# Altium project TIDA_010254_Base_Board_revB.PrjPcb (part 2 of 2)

## Sheet TIDA_010254_Base_Board_Sensors.SchDoc: Sensors
size 431 x 279 mm; Date: Not shown in title block; ApprovedBy: Not shown in title block; CheckedBy: Not shown in title block; Author: Not shown in title block; CompanyName: Not shown in title block; DrawnBy: Justin Yin; Engineer: Not shown in title block; Organization: Not shown in title block; Address1: Not shown in title block; Address2: Not shown in title block; Address3: Not shown in title block; Address4: Not shown in title block; DocumentNumber: 7; Revision: Use project parameter SCH_Rev; SheetNumber: 7; SheetTotal: 8; PageSetup: Record=PageOptions¦CenterHorizontal=True¦CenterVertical=True¦PrintScale=1.00¦XCorrection=1.00¦YCorrection=1.00¦PrintKind=0¦BorderSize=5000000¦LeftOffset=0¦BottomOffset=0¦Orientation=2¦PaperLength=1000¦PaperWidth=1000¦Scale=100¦PaperSource=15¦PrintQuality=600¦MediaType=1¦DitherType=10¦PaperKind=Letter¦PrintScaleMode=1
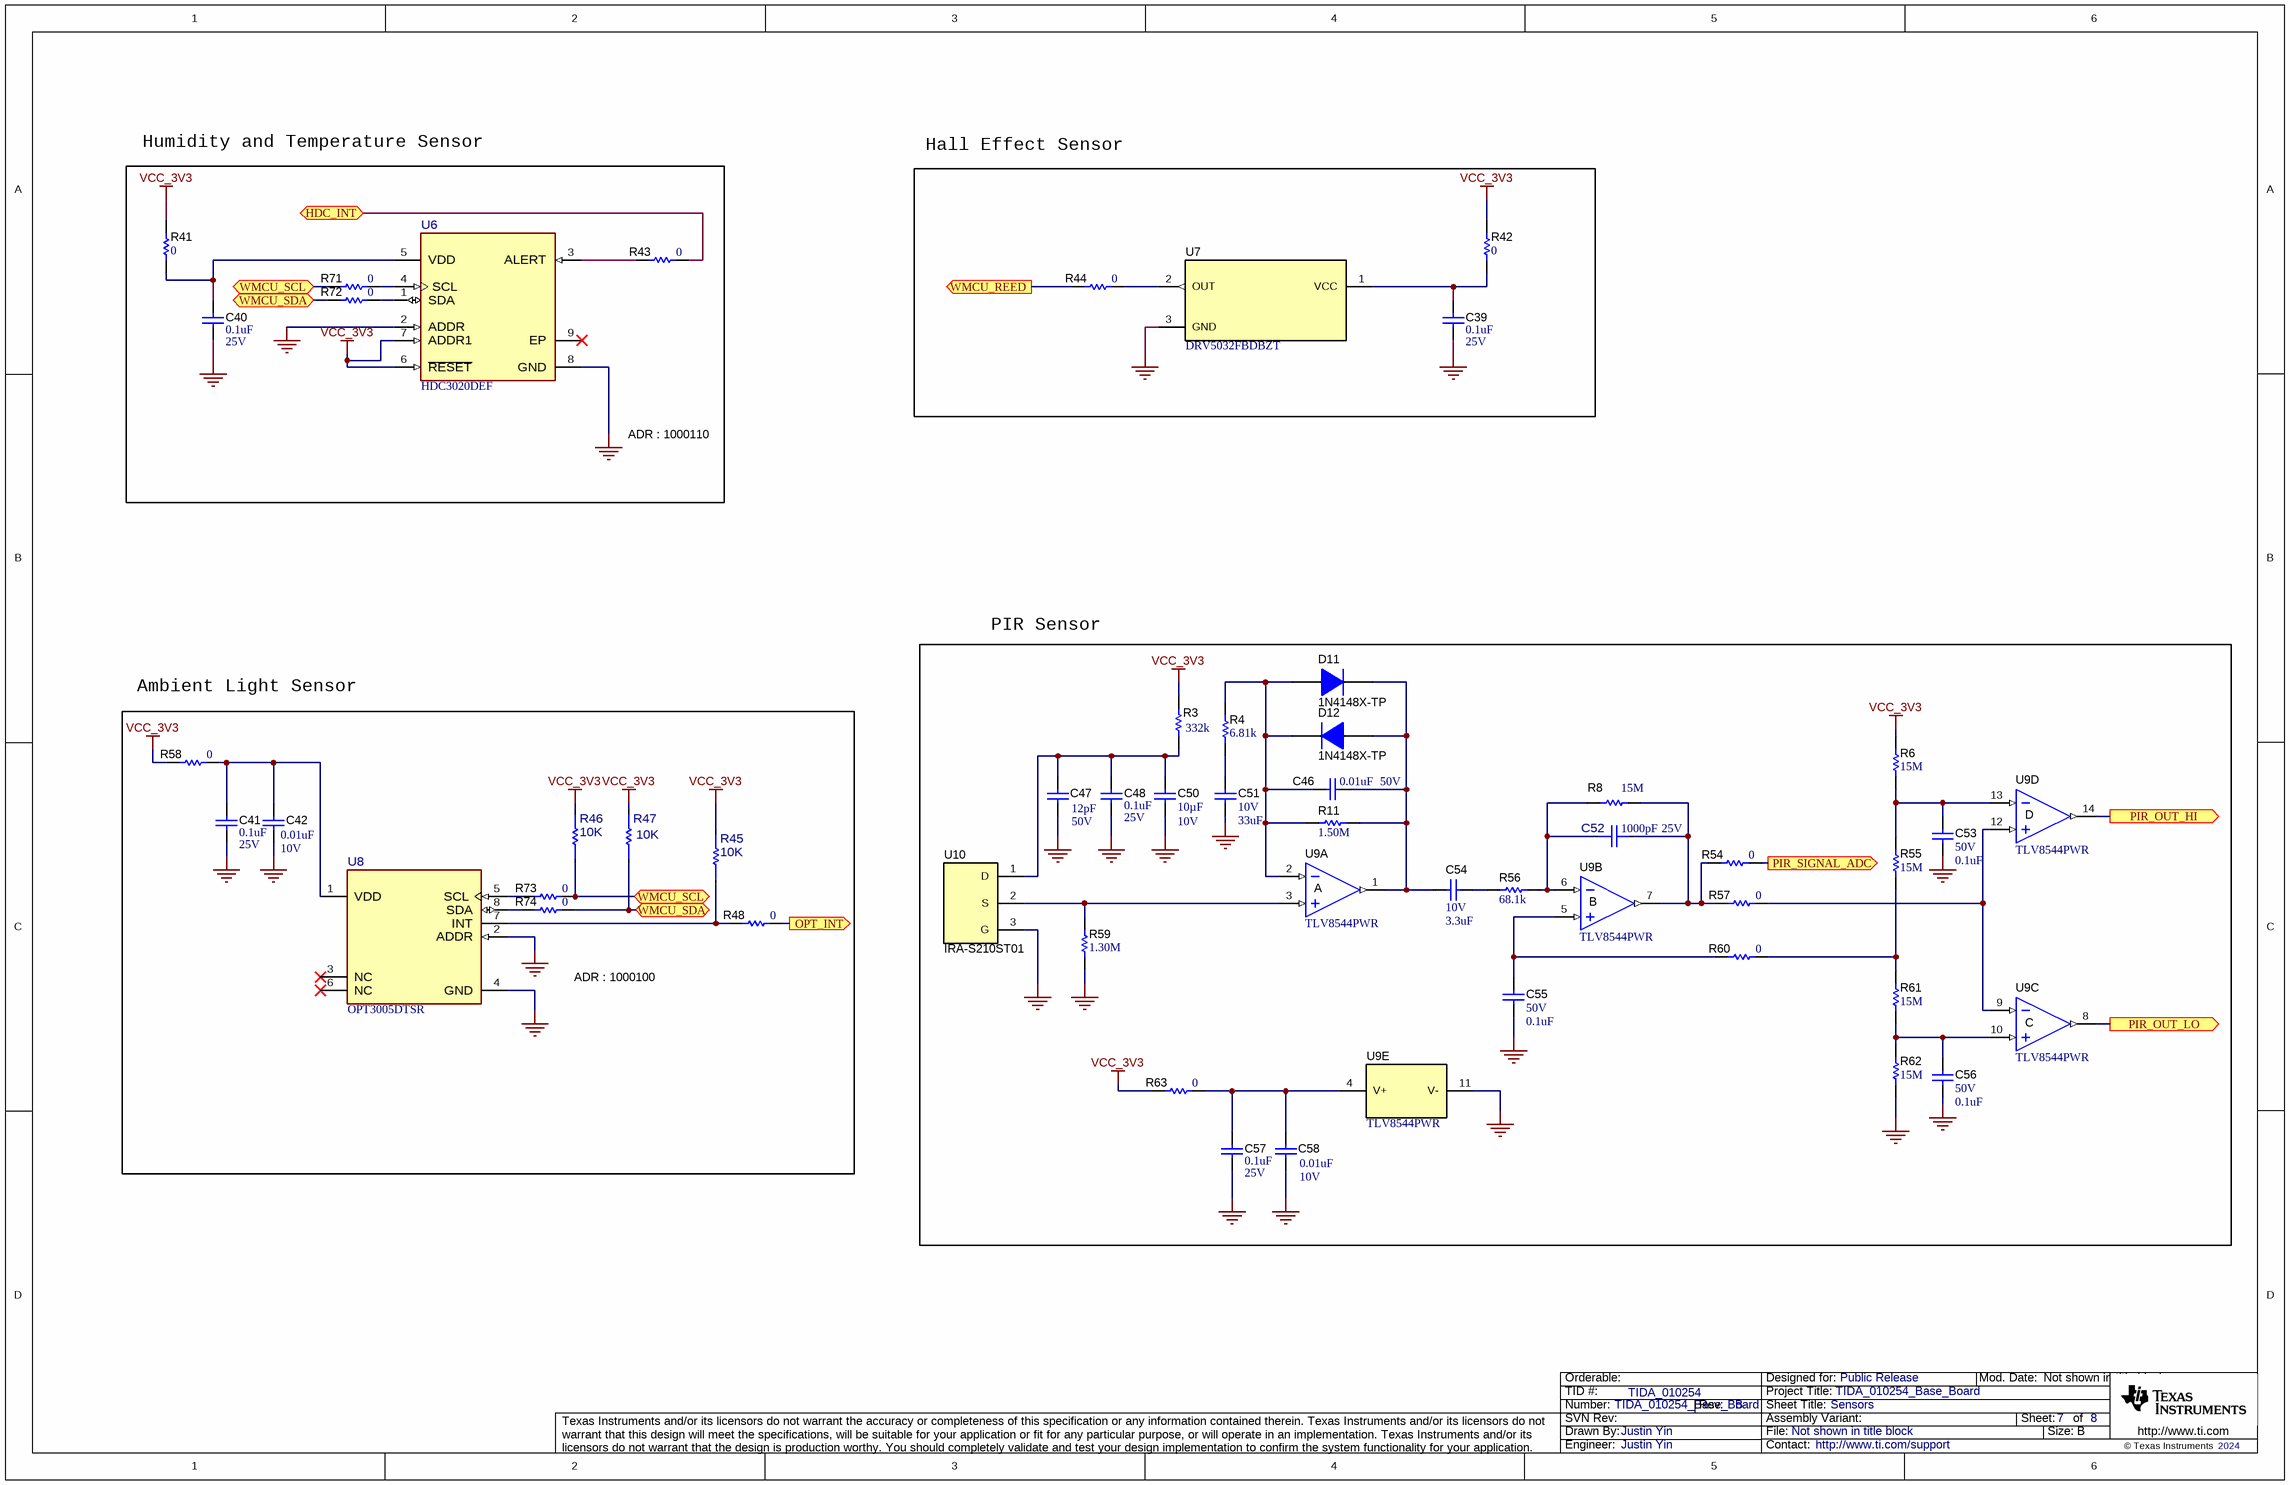
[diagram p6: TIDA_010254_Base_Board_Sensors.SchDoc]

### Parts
C39  VDC_V: 25V  ValueDisplayed: 0.1uF  [0402]  (hidden comment: GRM155R71E104KE14D)
C40  VDC_V: 25V  ValueDisplayed: 0.1uF  [0402]  (hidden comment: GRM155R71E104KE14D)
C41  VDC_V: 25V  ValueDisplayed: 0.1uF  [0402]  (hidden comment: GRM155R71E104KE14D)
C42  VDC_V: 10V  ValueDisplayed: 0.01uF  [0201]  (hidden comment: GRM033R61A103KA01D)
C46  VDC_V: 50V  ValueDisplayed: 0.01uF  [0402]  (hidden comment: GRM155R71H103KA88D)
C47  VDC_V: 50V  ValueDisplayed: 12pF  [0402]  (hidden comment: GRM1555C1H120JA01D)
C48  VDC_V: 25V  ValueDisplayed: 0.1uF  [0402]  (hidden comment: GRM155R71E104KE14D)
C50  Cap_F: 10µF  VDC_V: 10V  [0805_HV]  (hidden comment: GRM21BR71A106KA73L)
C51  VDC_V: 10V  ValueDisplayed: 33uF  [0805_HV]  (hidden comment: C2012X5R1A336M125AC)
C52  VDC_V: 25V  ValueDisplayed: 1000pF  [FP-GRM033R61E102KA01D_0201-MFG]  (hidden comment: GRM033R61E102KA01D)
C53  VDC_V: 50V  ValueDisplayed: 0.1uF  [0402]  (hidden comment: GRM155R71H104ME14D)
C54  VDC_V: 10V  ValueDisplayed: 3.3uF  [0402]  (hidden comment: C1005X5R1A335K050BC)
C55  VDC_V: 50V  ValueDisplayed: 0.1uF  [0402]  (hidden comment: GRM155R71H104ME14D)
C56  VDC_V: 50V  ValueDisplayed: 0.1uF  [0402]  (hidden comment: GRM155R71H104ME14D)
C57  VDC_V: 25V  ValueDisplayed: 0.1uF  [0402]  (hidden comment: GRM155R71E104KE14D)
C58  VDC_V: 10V  ValueDisplayed: 0.01uF  [0201]  (hidden comment: GRM033R61A103KA01D)
D11  1N4148X-TP  [SOD-523]
D12  1N4148X-TP  [SOD-523]
R3  ValueDisplayed: 332k  [0603]  (hidden comment: CRCW0603332KFKEA)
R4  ValueDisplayed: 6.81k  [0402]  (hidden comment: CRCW04026K81FKED)
R6  ValueDisplayed: 15M  [0805_HV]  (hidden comment: RMCF0805JT15M0)
R8  ValueDisplayed: 15M  [0805_HV]  (hidden comment: RMCF0805JT15M0)
R11  ValueDisplayed: 1.50M  [0402]  (hidden comment: RC0402FR-071M5L)
R41  ValueDisplayed: 0  [0402]  (hidden comment: RC0402JR-070RL)
R42  ValueDisplayed: 0  [0402]  (hidden comment: RC0402JR-070RL)
R43  ValueDisplayed: 0  [0402]  (hidden comment: RC0402JR-070RL)
R44  ValueDisplayed: 0  [0402]  (hidden comment: RC0402JR-070RL)
R45  10K  [FP-CRCW040210K0FKEDC_0402-MFG]
R46  10K  [FP-CRCW040210K0FKEDC_0402-MFG]
R47  10K  [FP-CRCW040210K0FKEDC_0402-MFG]
R48  ValueDisplayed: 0  [0402]  (hidden comment: RC0402JR-070RL)
R54  ValueDisplayed: 0  [0402]  (hidden comment: RC0402JR-070RL)
R55  ValueDisplayed: 15M  [0805_HV]  (hidden comment: RMCF0805JT15M0)
R56  ValueDisplayed: 68.1k  [0402]  (hidden comment: CRCW040268K1FKED)
R57  ValueDisplayed: 0  [0402]  (hidden comment: RC0402JR-070RL)
R58  ValueDisplayed: 0  [0402]  (hidden comment: RC0402JR-070RL)
R59  ValueDisplayed: 1.30M  [0402]  (hidden comment: CRCW04021M30FKED)
R60  ValueDisplayed: 0  [0402]  (hidden comment: RC0402JR-070RL)
R61  ValueDisplayed: 15M  [0805_HV]  (hidden comment: RMCF0805JT15M0)
R62  ValueDisplayed: 15M  [0805_HV]  (hidden comment: RMCF0805JT15M0)
R63  ValueDisplayed: 0  [0402]  (hidden comment: RC0402JR-070RL)
R71  ValueDisplayed: 0  [0402]  (hidden comment: RC0402JR-070RL)
R72  ValueDisplayed: 0  [0402]  (hidden comment: RC0402JR-070RL)
R73  ValueDisplayed: 0  [0402]  (hidden comment: RC0402JR-070RL)
R74  ValueDisplayed: 0  [0402]  (hidden comment: RC0402JR-070RL)
U6  HDC3020DEF  [DEF0008A-MFG]
U7  DRV5032FBDBZT  [DBZ0003A_N]
U8  OPT3005DTSR  [DTS0008A-MFG]
U9  TLV8544PWR  [PW0014A_N]  (parts A,B,C,D,E of 5)
U10  IRA-S210ST01  [Murata_IRA-E700ST0]

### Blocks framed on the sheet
Humidity and Temperature Sensor: C40 R41 R43 R71 R72 U6
Hall Effect Sensor: C39 R42 R44 U7
PIR Sensor: C46-C48 C50-C58 D11 D12 R3 R4 R6 R8 R11 R54-R57 R59-R63 U9 U10
Ambient Light Sensor: C41 C42 R45-R48 R58 R73 R74 U8

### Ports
HDC_INT (bidir), OPT_INT (out), PIR_OUT_HI (out), PIR_OUT_LO (out), PIR_SIGNAL_ADC (out), WMCU_REED (out), WMCU_SCL (bidir), WMCU_SDA (bidir)

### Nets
GND: C39.2 C40.2 C41.2 C42.2 C47.2 C48.2 C50.2 C51.2 C53.2 C55.2 C56.2 C57.2 C58.2 R59.1 R62.1 U6.2(ADDR) U6.8(GND) U7.3(GND) U8.2(ADDR) U8.4(GND) U9.11(V-) U10.3(G)
VCC_3V3: R3.2 R6.2 R41.2 R42.2 R45.2 R46.2 R47.2 R58.1 R63.1 U6.6(~{RESET}) U6.7(ADDR1)
HDC_INT: R43.2 ; port HDC_INT
OPT_INT: R48.2 ; port OPT_INT
PIR_OUT_HI: U9.14(OUT) ; port PIR_OUT_HI
PIR_OUT_LO: U9.8(OUT) ; port PIR_OUT_LO
PIR_SIGNAL_ADC: R54.2 ; port PIR_SIGNAL_ADC
WMCU_REED: R44.1 ; port WMCU_REED
WMCU_SCL: R46.1 R71.1 R73.2 ; port WMCU_SCL
WMCU_SDA: R47.1 R72.1 R74.2 ; port WMCU_SDA
NetC39_1: C39.1 R42.1 U7.1(VCC)
NetC40_1: C40.1 R41.1 U6.5(VDD)
NetC41_1: C41.1 C42.1 R58.2 U8.1(VDD)
NetC46_1: C46.1 C54.2 D11.1(K) D12.2(A) R11.2 U9.1(OUT)
NetC46_2: C46.2 D11.2(A) D12.1(K) R4.2 R11.1 U9.2(IN-)
NetC47_1: C47.1 C48.1 C50.1 R3.1 U10.1(D)
NetC51_1: C51.1 R4.1
NetC52_1: C52.1 R8.1 R56.2 U9.6(IN-)
NetC52_2: C52.2 R8.2 R54.1 R57.1 U9.7(OUT)
NetC53_1: C53.1 R6.1 R55.2 U9.13(IN-)
NetC54_1: C54.1 R56.1
NetC55_1: C55.1 R60.1 U9.5(IN+)
NetC56_1: C56.1 R61.1 R62.2 U9.10(IN+)
NetC57_1: C57.1 C58.1 R63.2 U9.4(V+)
NetR43_1: R43.1 U6.3(ALERT)
NetR44_2: R44.2 U7.2(OUT)
NetR45_1: R45.1 R48.1 U8.7(INT)
NetR55_1: R55.1 R60.2 R61.2
NetR57_2: R57.2 U9.9(IN-) U9.12(IN+)
NetR59_2: R59.2 U9.3(IN+) U10.2(S)
NetR71_2: R71.2 U6.4(SCL)
NetR72_2: R72.2 U6.1(SDA)
NetR73_1: R73.1 U8.5(SCL)
NetR74_1: R74.1 U8.8(SDA)

Not connected (* = marked no-connect by the designer): U6 9(EP)*; U8 3(NC)* 6(NC)*

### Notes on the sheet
- ADR : 1000110
- ADR : 1000100

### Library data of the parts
C39-C41 C48 C57 = CMP-0006659-2: CAP, CERM, 0.1 uF, 25 V, +/- 10%, X7R, 0402; Manufacturer: MuRata; TaMin_C: -55°C; Polarized: N; SizeAreaWB_mm2: 3; Value1: Unknown; U/M: EA; Value: 0.1uF; TaMax_C: 125°C; SizeZ_mm: 0.6; SizeX_mm: 1; SizeY_mm: 0.5; Cap_F: 100nF; AEC Category: Q200
C42 C58 = CMP-0009703-2: CAP, CERM, 0.01 uF, 10 V, +/- 10%, X5R, 0201; Manufacturer: MuRata; TaMin_C: -55°C; Polarized: N; SizeAreaWB_mm2: 2.08; Value1: Unknown; U/M: EA; Value: 0.01uF; TaMax_C: 85°C; SizeZ_mm: 0.26; SizeX_mm: 0.6; SizeY_mm: 0.3; SizeArea_mm2: 0.18; Cap_F: 10nF; AEC Category: Q200
C46 = CMP-0006674-2: CAP, CERM, 0.01 uF, 50 V, +/- 10%, X7R, 0402; Manufacturer: MuRata; TaMin_C: -55°C; Polarized: N; SizeAreaWB_mm2: 3; Value1: Unknown; U/M: EA; Value: 0.01uF; TaMax_C: 125°C; SizeZ_mm: 0.6; SizeX_mm: 1; SizeY_mm: 0.5; Cap_F: 10nF; AEC Category: Q200
C47 = CMP-0006415-2: CAP, CERM, 12 pF, 50 V, +/- 5%, C0G/NP0, 0402; Manufacturer: MuRata; TaMin_C: -55°C; Polarized: N; SizeAreaWB_mm2: 3; Value1: Unknown; U/M: EA; Value: 12pF; TaMax_C: 125°C; SizeZ_mm: 0.6; SizeX_mm: 1; SizeY_mm: 0.5; AEC Category: Q200
C50 = CMP-0081849-1: CAP, CERM, 10 µF,  V,+/- 10%, X7R, 0805; Manufacturer: MuRata; TaMin_C: -55°C; Polarized: N; Green_Lifecycle: Active; SizeAreaWB_mm2: 6.75; Green_REACh: Passed; U/M: EA; Value: 10uF; TaMax_C: 125°C; SizeZ_mm: 1.45; SizeX_mm: 2; SizeY_mm: 1.25; Cap_Case: 0805; SizeArea_mm2: 2.5; AEC Category: Q200
C51 = CMP-0007824-2: CAP, CERM, 33 uF, 10 V, +/- 20%, X5R, 0805; Manufacturer: TDK; TaMin_C: -55°C; ESR_ohm: 1.694m; Polarized: N; SizeAreaWB_mm2: 6.75; Value1: 0.001694 ohm; U/M: EA; Value: 33uF; TaMax_C: 85°C; SizeZ_mm: 1.45; SizeX_mm: 2; SizeY_mm: 1.25; Cap_Case: 0805; SizeArea_mm2: 2.5; Cap_F: 33µF; IRMS_A: 5.01281A; AEC Category: Q200
C52 = CMP-0098152-1: Chip Multilayer Ceramic Capacitors for General Purpose, 0201, 1000pF, X5R, 15%, 10%, 25V; Manufacturer: Murata; SizeZ_mm: 0.33mm; Cap_F: 1nF; Value: 1nF; AEC Qualified: No
C53 C55 C56 = CMP-0006675-2: CAP, CERM, 0.1 uF, 50 V, +/- 20%, X7R, 0402; Manufacturer: MuRata; TaMin_C: -55°C; Polarized: N; SizeAreaWB_mm2: 3; Value1: Unknown; U/M: EA; Value: 0.1uF; TaMax_C: 125°C; SizeZ_mm: 0.6; SizeX_mm: 1; SizeY_mm: 0.5; Cap_F: 100nF; AEC Category: Q200
C54 = CMP-0006265-2: CAP, CERM, 3.3 uF, 10 V, +/- 10%, X5R, 0402; Manufacturer: TDK; TaMin_C: -55°C; ESR_ohm: 4.157m; Polarized: N; SizeAreaWB_mm2: 3; Value1: 0.004157 ohm; U/M: EA; Value: 3.3uF; TaMax_C: 85°C; SizeZ_mm: 0.6; SizeX_mm: 1; SizeY_mm: 0.5; Cap_F: 3.3µF; IRMS_A: 2.45391A; AEC Category: Q200
D11 D12 = CMP-0076957-3: Diode, Switching, 75 V, 0.3 A, SOD-523; Manufacturer: Micro Commercial Components; SizeY_mm: 0.9; Value2: 1.25V; Vr_V: 75V; Value1: 0.3A; Value: 75V; Green_Lifecycle: Not Set; SizeAreaWB_mm2: 5.13; SizeArea_mm2: 1.53; SizeZ_mm: 0.65; Io_A: 300mA; TJmax_C: 150°C; SizeX_mm: 1.7; Green_REACh: Incomplete; AEC Category: Q101
R3 = CMP-0022336-4: RES, 332 k, 1%, 0.1 W, AEC-Q200 Grade 0, 0603; Manufacturer: Vishay-Dale; Power_W: 100mW; TempCo: 100 ppm/C; Value: 332k; EIA_Code: E96; SizeX_mm: 1.6; SizeY_mm: 0.8; SizeZ_mm: 1; Value2: 0.1W; SizeArea_mm2: 1.28; AEC Qualified: Y; VDC_V: 75V; AEC Category: Q200; AEC Grade: 0
R4 = CMP-0026517-2: RES, 6.81 k, 1%, 0.063 W, AEC-Q200 Grade 0, 0402; Manufacturer: Vishay-Dale; Power_W: 63mW; TempCo: 100 ppm/C; Value_Code: 6k81; Value: 6.81k; EIA_Code: E96; SizeX_mm: 1; SizeY_mm: 0.5; SizeZ_mm: 0.6; Value2: 0.063W; AEC Qualified: Y; VDC_V: 50V; AEC Category: Q200; AEC Grade: 0
R6 R8 R55 R61 R62 = CMP-0020831-2: RES, 15 M, 5%, 0.125 W, AEC-Q200 Grade 0, 0805; Manufacturer: Stackpole Electronics Inc; Power_W: 125mW; TempCo: 200 ppm/C; Value_Code: 15M0; U/M: EA; Value: 15Meg; SizeX_mm: 2; SizeY_mm: 1.25; SizeZ_mm: 1.45; Value2: 0.125W; SizeArea_mm2: 2.5; AEC Qualified: Y; VDC_V: 75V; AEC Grade: 0; AEC Category: Q200
R11 = CMP-0026726-1: RES, 1.50 M, 1%, 0.063 W, 0402; Manufacturer: Yageo America; Power_W: 63mW; TempCo: 100 ppm/C; Value_Code: 1M50; U/M: EA; Value: 1.50Meg; EIA_Code: E96; Res_ohm: 1.5M; SizeX_mm: 1; SizeY_mm: 0.5; SizeZ_mm: 0.6; Value2: 0.063W; AEC Qualified: N; VDC_V: 50V; AEC Category: Q200
R41-R44 R48 R54 R57 R58 R60 R63 R71-R74 = CMP-0027004-2: RES, 0, 5%, 0.063 W, 0402; Manufacturer: Yageo America; Power_W: 63mW; TempCo: 200 ppm/C; Value_Code: 0000; U/M: EA; Value: 0; EIA_Code: E24; SizeX_mm: 1; SizeY_mm: 0.5; SizeZ_mm: 0.6; Value2: 0.063W; VDC_V: 50V; AEC Category: Q200
R45-R47 = CMP-0094735-1: 10 kOhms ±1% 0.063W, 1/16W Chip Resistor 0402 (1005 Metric)  Thick Film; PartNumber: CRCW040210K0FKEDC; Manufacturer: Vishay; SizeZ_mm: 0.4mm; Power_W: 63mW; VDC_V: 50V; AEC Grade: Grade 0; TempCo: 100ppm/°C; AEC Qualified: Yes
R56 = CMP-0026506-2: RES, 68.1 k, 1%, 0.063 W, AEC-Q200 Grade 0, 0402; Manufacturer: Vishay-Dale; Power_W: 63mW; TempCo: 100 ppm/C; Value_Code: 68k1; Value: 68.1k; EIA_Code: E96; SizeX_mm: 1; SizeY_mm: 0.5; SizeZ_mm: 0.6; Value2: 0.063W; AEC Qualified: Y; VDC_V: 50V; AEC Category: Q200; AEC Grade: 0
R59 = CMP-0026111-2: RES, 1.30 M, 1%, 0.063 W, AEC-Q200 Grade 0, 0402; Manufacturer: Vishay-Dale; Power_W: 63mW; TempCo: 100 ppm/C; Value_Code: 1M30; Value: 1.30Meg; EIA_Code: E96; Res_ohm: 1.3M; SizeX_mm: 1; SizeY_mm: 0.5; SizeZ_mm: 0.6; Value2: 0.063W; AEC Qualified: Y; VDC_V: 50V; AEC Category: Q200; AEC Grade: 0
U6 = CMP-0087942-2: Integrated Humidity and Temperature Digital Sensor; Manufacturer: Texas Instruments; AEC Category: Q200; AEC Qualified: No; SizeZ_mm: 0.8mm; CompType: IC
U7 = CMP-0078026-1: Ultra-Low Power 1.65V to 5.5V Hall Effect Switch Sensor, DBZ0003A (SOT-23-3); Alternate Manufacturer: Texas Instruments; SizeAreaWB_mm2: 14; SizeZ_mm: 1.12; SizeX_mm: 2.5; SizeY_mm: 3; SizeArea_mm2: 7.5; CompType: IC; AEC Qualified: N; AEC Category: Q200
U8 = CMP-0095235-1: Ambient Light Sensor (ALS) With Excellent Angular IR Rejection 1.6-3.6V 1.8-3.7mA I2C; Manufacturer: Texas Instruments; Standoff Height: 0mm; SizeZ_mm: 0.6mm; Sensor Output: I2C,SMBus; TJmax_C: +150°C; Max Supply Voltage: 3.6V; AEC Qualified: No; Min Supply Voltage: 1.6V; Operating Supply Current: 1.8-3.7uA
U9 = CMP-0013616-3: 500 nA RRIO Nanopower Operational Amplifier, PW0014A (TSSOP-14); Manufacturer: Texas Instruments; Alternate PartNumber: TLV8544PWT; SizeX_mm: 6.4; SizeY_mm: 5; CompType: IC; SizeZ_mm: 1.2; SizeArea_mm2: 32; SizeAreaWB_mm2: 58.8; U/M: EA
U10 = CMP-0080109-2: Pyro Electric Infrared Sensor Fresnel Lens, TH; Manufacturer: MuRata; SizeArea_mm2: 84.64; SizeAreaWB_mm2: 125.44; SizeY_mm: 9.2; SizeZ_mm: 4.9

## Sheet TIDA_010254_Base_Board_Hardware.SchDoc: HARDWARE
size 431 x 279 mm; Date: Not shown in title block; ApprovedBy: Not shown in title block; CheckedBy: Not shown in title block; Author: Not shown in title block; CompanyName: Not shown in title block; DrawnBy: Justin Yin; Engineer: Not shown in title block; Organization: Not shown in title block; Address1: Not shown in title block; Address2: Not shown in title block; Address3: Not shown in title block; Address4: Not shown in title block; DocumentNumber: 8; Revision: Use project parameter SCH_Rev; SheetNumber: 8; SheetTotal: 8; PageSetup: Record=PageOptions¦CenterHorizontal=True¦CenterVertical=True¦PrintScale=1.00¦XCorrection=1.00¦YCorrection=1.00¦PrintKind=0¦BorderSize=5000000¦LeftOffset=0¦BottomOffset=0¦Orientation=2¦PaperLength=1000¦PaperWidth=1000¦Scale=100¦PaperSource=15¦PrintQuality=600¦MediaType=1¦DitherType=10¦PaperKind=Letter¦PrintScaleMode=1
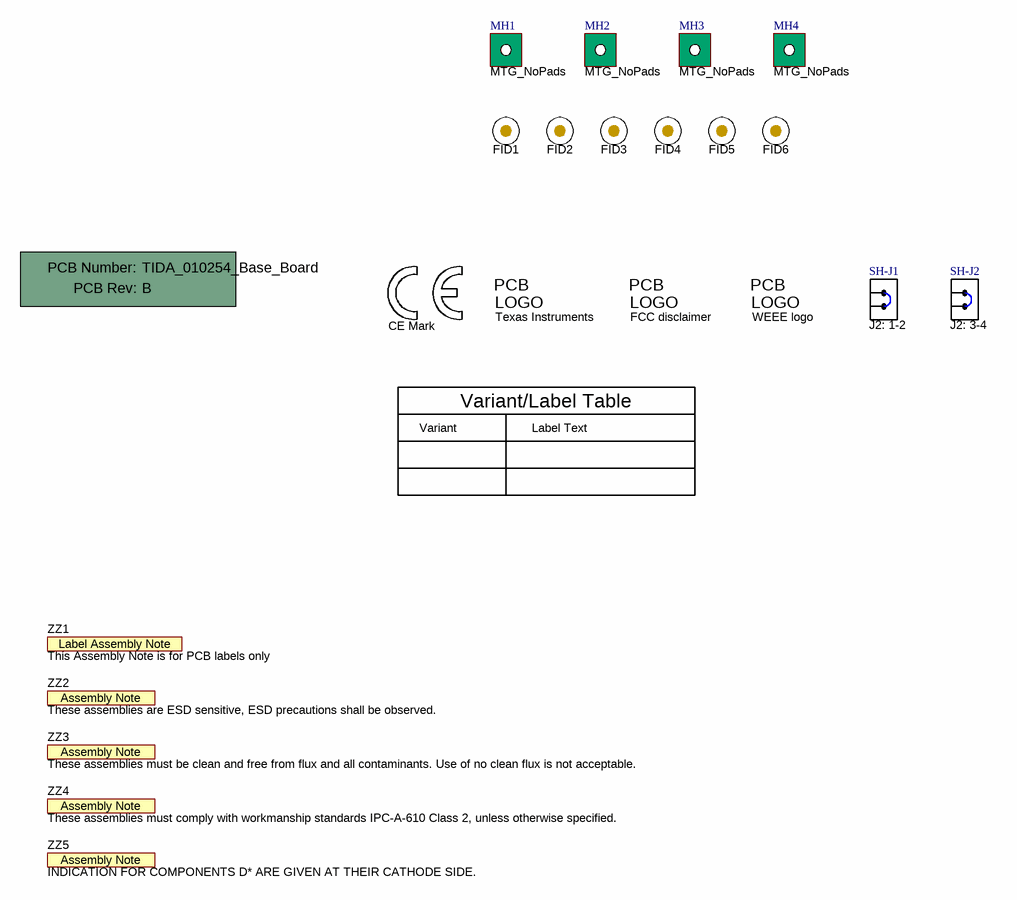
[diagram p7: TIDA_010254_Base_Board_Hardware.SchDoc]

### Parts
!PCB1  Printed Circuit Board  (value not drawn)  (mechanical)
FID1  Fiducial  [Fiducial10-20]  (value not drawn)
FID2  Fiducial  [Fiducial10-20]  (value not drawn)
FID3  Fiducial  [Fiducial10-20]  (value not drawn)
FID4  Fiducial  [Fiducial10-20]  (value not drawn)
FID5  Fiducial  [Fiducial10-20]  (value not drawn)
FID6  Fiducial  [Fiducial10-20]  (value not drawn)
Logo1  CE Mark  [CE_Mark_5mm]  (no BOM)
Logo5  Texas Instruments  [TI_Stacked_Overlay_Small]  (no BOM)
Logo7  FCC disclaimer  [FCC_disclaimer]  (no BOM)
Logo8  WEEE logo  [WEEE_Minimum]  (no BOM)
MH1  MTG_NoPads  [NPTH125mil]  (no BOM)
MH2  MTG_NoPads  [NPTH125mil]  (no BOM)
MH3  MTG_NoPads  [NPTH125mil]  (no BOM)
MH4  MTG_NoPads  [NPTH125mil]  (no BOM)
SH-J1  J2: 1-2  [SNT-100-BK-G]
SH-J2  J2: 3-4  [SNT-100-BK-G]
ZZ1  This Assembly Note is for PCB labels only  [AssemblyNoteLabel]  (no BOM)
ZZ2  These assemblies are ESD sensitive, ESD precautions shall be observed.  [AssemblyNote]  (no BOM)
ZZ3  These assemblies must be clean and free from flux and all contaminants. Use of no clean flux is not acceptable.  [AssemblyNote]  (no BOM)
ZZ4  These assemblies must comply with workmanship standards IPC-A-610 Class 2, unless otherwise specified.  [AssemblyNote]  (no BOM)
ZZ5  INDICATION FOR COMPONENTS D* ARE GIVEN AT THEIR CATHODE SIDE.  [AssemblyNote]  (no BOM)

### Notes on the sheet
- Variant
- Variant/Label Table
- Label Text

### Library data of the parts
!PCB1 = CMP-0003618-2: Manufacturer: Any; PartNumber: TIDA_010254_Base_Board
FID1-FID6 = CMP-0077181-1: Fiducial mark.  There is nothing to buy or mount.
Logo1 = CMP-0074844-2: Manufacturer: Texas Instruments; SymbolCreator: a0412235; AEC Category: Q200; CompType: IC
Logo5 = CMP-0074838-1: Texas Instrument Corporate Signature; SymbolCreator: a0412235; Lib Reference: TI_Logo; Library Reference: Logo
Logo7 = CMP-0074847-1: FCC_disclaimer; Library Reference: Logo
Logo8 = CMP-0074769-4: Manufacturer: Texas Instruments; CompType: IC; AEC Category: Q200
MH1-MH4 = CMP-0078424-2: PCB Mounting Hole, No Pad; Manufacturer: Any; Key: Mounting Hole (non-standard) No Pad
SH-J1 SH-J2 = CMP-0003623-3: Shunt, 100mil, Gold plated, Black; Alternate PartNumber: 969102-0000-DA; Manufacturer: Samtec; Alternate Manufacturer: 3M; Value: 1x2; Note: You can "mate" this to a header by matching the designator.  i.e. use SH-J3 for header J3
ZZ1 = CMP-0003616-3
ZZ2 = CMP-0077236-1
ZZ3 = CMP-0077237-1
ZZ4 ZZ5 = CMP-0077238-1

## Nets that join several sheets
GND: TIDA_010254_Base_Board_Connector (14 pins), TIDA_010254_Base_Board_Charger (33 pins), TIDA_010254_Base_Board_DC_Regulators (18 pins), TIDA_010254_Base_Board_CC1352R (46 pins), TIDA_010254_Base_Board_Sensors (22 pins)
SYS_POWER: TIDA_010254_Base_Board_Charger (7 pins), TIDA_010254_Base_Board_DC_Regulators (9 pins), TIDA_010254_Base_Board_CC1352R (R34.2)
VCC_3V3: TIDA_010254_Base_Board_Connector (C1.1 FB3.1 FB4.1 J4.2), TIDA_010254_Base_Board_DC_Regulators (9 pins), TIDA_010254_Base_Board_CC1352R (11 pins), TIDA_010254_Base_Board_Sensors (11 pins)
HDC_INT: TIDA_010254_Base_Board_CC1352R (U4.38), TIDA_010254_Base_Board_Sensors (R43.2)
LVDS_D1_XDS_UARTA_RX_CAN_RX: TIDA_010254_Base_Board_Connector (J1.6), TIDA_010254_Base_Board_CC1352R (R68.1)
LVDS_D2_XDS_UARTA_TX_CAN_TX: TIDA_010254_Base_Board_Connector (J1.8), TIDA_010254_Base_Board_CC1352R (R67.1)
MODE: TIDA_010254_Base_Board_DC_Regulators (R53.2 U3.B1), TIDA_010254_Base_Board_CC1352R (U4.28)
OPT_INT: TIDA_010254_Base_Board_CC1352R (U4.36), TIDA_010254_Base_Board_Sensors (R48.2)
PIR_OUT_HI: TIDA_010254_Base_Board_CC1352R (U4.29), TIDA_010254_Base_Board_Sensors (U9.14)
PIR_OUT_LO: TIDA_010254_Base_Board_CC1352R (U4.30), TIDA_010254_Base_Board_Sensors (U9.8)
PIR_SIGNAL_ADC: TIDA_010254_Base_Board_CC1352R (U4.43), TIDA_010254_Base_Board_Sensors (R54.2)
SPI_CS: TIDA_010254_Base_Board_Connector (R65.2), TIDA_010254_Base_Board_CC1352R (U4.32)
WMCU_FLASH_CLK: TIDA_010254_Base_Board_Connector (R64.2), TIDA_010254_Base_Board_CC1352R (U4.16 U5.6)
WMCU_FLASH_MISO: TIDA_010254_Base_Board_Connector (R18.2), TIDA_010254_Base_Board_CC1352R (U4.14 U5.2)
WMCU_FLASH_MOSI: TIDA_010254_Base_Board_Connector (R17.2), TIDA_010254_Base_Board_CC1352R (U4.15 U5.5)
WMCU_REED: TIDA_010254_Base_Board_CC1352R (U4.37), TIDA_010254_Base_Board_Sensors (R44.1)
WMCU_RX: TIDA_010254_Base_Board_Connector (J2.1), TIDA_010254_Base_Board_CC1352R (U4.39)
WMCU_SCL: TIDA_010254_Base_Board_CC1352R (U4.21), TIDA_010254_Base_Board_Sensors (R46.1 R71.1 R73.2)
WMCU_SDA: TIDA_010254_Base_Board_CC1352R (U4.20), TIDA_010254_Base_Board_Sensors (R47.1 R72.1 R74.2)
WMCU_TX: TIDA_010254_Base_Board_Connector (J2.3), TIDA_010254_Base_Board_CC1352R (U4.40)

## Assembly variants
001: not fitted BT2 C29 C33 C34 FID1 FID2 FID3 FID4 FID5 FID6 J12 J15 R10 R52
